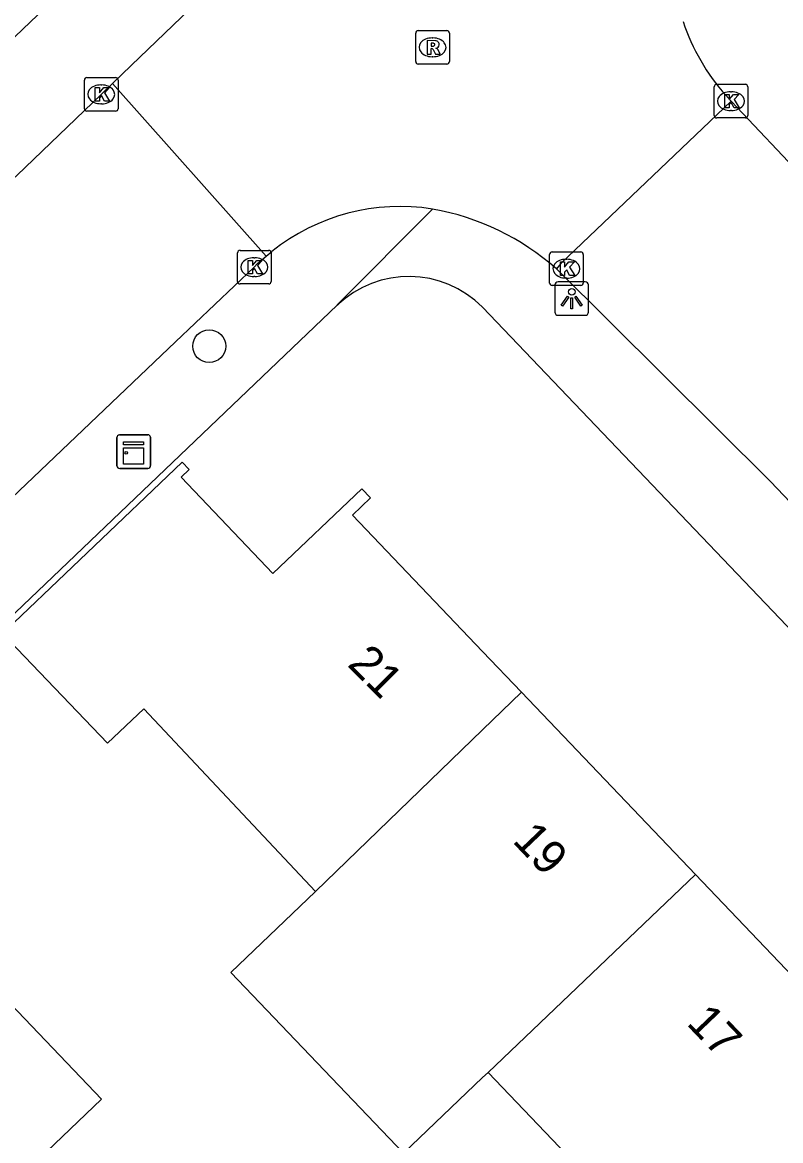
# Model space of a CAD drawing. Extents: x 159353 to 160616, y 385893 to 387321.
# Drawn here: x 159986.31 to 160008.86, y 386452.66 to 386485.93 of the extents above; entities that cross this region are included whole.
import ezdxf

# ---------------------------------------------------------------- set-up
doc = ezdxf.new("R2010")
doc.units = 0
for name, color, linetype in [('IMGEO_Boom', 7, 'Continuous'), ('IMGEO_Kast', 7, 'Continuous'), ('IMGEO_Kolk', 7, 'Continuous'), ('IMGEO_Lichtpunt', 7, 'Continuous'), ('IMGEO_Pand', 7, 'Continuous'), ('IMGEO_Pand_nummerreeks', 7, 'Continuous'), ('IMGEO_Rijbaan_lokaal_open', 7, 'Continuous'), ('IMGEO_Rioolput', 7, 'Continuous'), ('IMGEO_Voetpad_open', 7, 'Continuous')]:
    doc.layers.add(name, color=color, linetype=linetype)

msp = doc.modelspace()

# ---------------------------------------------------------------- linework, layer by layer
at = {"layer": 'IMGEO_Boom'}
msp.add_circle((159991.869, 386476.297), 0.489, dxfattribs=at)
at = {"layer": 'IMGEO_Kast'}
for p, q in [((159989.121, 386472.735), (159989.121, 386473.576)), ((159989.121, 386473.576), (159989.121, 386472.735)), ((159989.196, 386473.66), (159990.037, 386473.66)), ((159990.037, 386473.66), (159989.196, 386473.66)), ((159990.121, 386473.585), (159990.121, 386472.744)), ((159990.121, 386472.744), (159990.121, 386473.585)), ((159990.046, 386472.66), (159989.205, 386472.66)), ((159989.205, 386472.66), (159990.046, 386472.66))]:
    msp.add_line(p, q, dxfattribs=at)
for points in [[(159989.316, 386473.45), (159989.916, 386473.45), (159989.916, 386473.365), (159989.316, 386473.365), (159989.316, 386473.45)], [(159989.316, 386473.275), (159989.916, 386473.275), (159989.916, 386472.786), (159989.316, 386472.786), (159989.316, 386473.275)]]:
    msp.add_lwpolyline(points, dxfattribs=at)
msp.add_circle((159989.4, 386473.124), 0.0377, dxfattribs=at)
for centre, start, end in [((159989.199, 386473.582), 92.4484, 184.2845), ((159989.199, 386473.582), 92.4484, 184.2845), ((159990.043, 386473.582), 2.4484, 94.2845), ((159990.043, 386473.582), 2.4484, 94.2845), ((159989.199, 386472.738), 182.4484, 274.2845), ((159989.199, 386472.738), 182.4484, 274.2845), ((159990.043, 386472.738), 272.4484, 4.2845), ((159990.043, 386472.738), 272.4484, 4.2845)]:
    msp.add_arc(centre, 0.0779, start, end, dxfattribs=at)
at = {"layer": 'IMGEO_Kolk'}
for p, q in [((159988.156, 386483.363), (159988.156, 386484.215)), ((159988.231, 386484.289), (159989.083, 386484.289)), ((159989.157, 386484.215), (159989.157, 386483.363)), ((159988.644, 386484.069), (159988.669, 386484.069)), ((160006.887, 386483.161), (160006.887, 386484.013)), ((160006.962, 386484.087), (160007.814, 386484.087)), ((160007.375, 386483.867), (160007.4, 386483.867)), ((160007.888, 386484.013), (160007.888, 386483.161)), ((159988.667, 386483.509), (159988.642, 386483.509)), ((159989.083, 386483.289), (159988.231, 386483.289)), ((160007.398, 386483.307), (160007.373, 386483.307)), ((160007.814, 386483.087), (160006.962, 386483.087)), ((159992.784, 386479.148), (159993.636, 386479.148)), ((159992.709, 386478.222), (159992.709, 386479.074)), ((159993.197, 386478.928), (159993.222, 386478.928)), ((159993.71, 386479.074), (159993.71, 386478.222)), ((160001.993, 386478.176), (160001.993, 386479.028)), ((160002.068, 386479.102), (160002.92, 386479.102)), ((160002.481, 386478.882), (160002.506, 386478.882)), ((160002.994, 386479.028), (160002.994, 386478.176)), ((159993.636, 386478.148), (159992.784, 386478.148)), ((159993.22, 386478.368), (159993.195, 386478.368)), ((160002.504, 386478.322), (160002.479, 386478.322)), ((160002.92, 386478.102), (160002.068, 386478.102))]:
    msp.add_line(p, q, dxfattribs=at)
for points in [[(159988.156, 386483.363), (159988.156, 386484.215)], [(159988.231, 386484.289), (159989.083, 386484.289)], [(159989.157, 386484.215), (159989.157, 386483.363)], [(159988.477, 386483.989), (159988.6, 386483.989), (159988.6, 386483.838), (159988.73, 386483.989), (159988.894, 386483.989), (159988.748, 386483.838), (159988.901, 386483.589), (159988.749, 386483.589), (159988.664, 386483.753), (159988.6, 386483.686), (159988.6, 386483.589), (159988.477, 386483.589), (159988.477, 386483.989)], [(160006.887, 386483.161), (160006.887, 386484.013)], [(160006.962, 386484.087), (160007.814, 386484.087)], [(160007.888, 386484.013), (160007.888, 386483.161)], [(160007.208, 386483.787), (160007.331, 386483.787), (160007.331, 386483.636), (160007.461, 386483.787), (160007.625, 386483.787), (160007.479, 386483.636), (160007.632, 386483.387), (160007.48, 386483.387), (160007.395, 386483.551), (160007.331, 386483.484), (160007.331, 386483.387), (160007.208, 386483.387), (160007.208, 386483.787)], [(159989.083, 386483.289), (159988.231, 386483.289)], [(160007.814, 386483.087), (160006.962, 386483.087)], [(159992.784, 386479.148), (159993.636, 386479.148)], [(159992.709, 386478.222), (159992.709, 386479.074)], [(159993.03, 386478.848), (159993.153, 386478.848), (159993.153, 386478.697), (159993.283, 386478.848), (159993.447, 386478.848), (159993.301, 386478.697), (159993.454, 386478.448), (159993.302, 386478.448), (159993.217, 386478.612), (159993.153, 386478.545), (159993.153, 386478.448), (159993.03, 386478.448), (159993.03, 386478.848)], [(159993.71, 386479.074), (159993.71, 386478.222)], [(160001.993, 386478.176), (160001.993, 386479.028)], [(160002.068, 386479.102), (160002.92, 386479.102)], [(160002.994, 386479.028), (160002.994, 386478.176)], [(160002.314, 386478.802), (160002.437, 386478.802), (160002.437, 386478.651), (160002.567, 386478.802), (160002.731, 386478.802), (160002.585, 386478.651), (160002.738, 386478.402), (160002.586, 386478.402), (160002.501, 386478.566), (160002.437, 386478.499), (160002.437, 386478.402), (160002.314, 386478.402), (160002.314, 386478.802)], [(159993.636, 386478.148), (159992.784, 386478.148)], [(160002.92, 386478.102), (160002.068, 386478.102)]]:
    msp.add_lwpolyline(points, dxfattribs=at)
for centre, start, end in [((159988.233, 386484.213), 91.552, 178.448), ((159988.233, 386484.213), 91.552, 178.448), ((159989.081, 386484.213), 1.552, 88.448), ((159989.081, 386484.213), 1.552, 88.448), ((160006.964, 386484.011), 91.552, 178.448), ((160006.964, 386484.011), 91.552, 178.448), ((160007.812, 386484.011), 1.552, 88.448), ((160007.812, 386484.011), 1.552, 88.448), ((159988.233, 386483.365), 181.552, 268.448), ((159988.233, 386483.365), 181.552, 268.448), ((159989.081, 386483.365), 271.552, 358.448), ((159989.081, 386483.365), 271.552, 358.448), ((160006.964, 386483.163), 181.552, 268.448), ((160006.964, 386483.163), 181.552, 268.448), ((160007.812, 386483.163), 271.552, 358.448), ((160007.812, 386483.163), 271.552, 358.448), ((159992.786, 386479.072), 91.552, 178.448), ((159992.786, 386479.072), 91.552, 178.448), ((159993.634, 386479.072), 1.552, 88.448), ((159993.634, 386479.072), 1.552, 88.448), ((160002.07, 386479.026), 91.552, 178.448), ((160002.07, 386479.026), 91.552, 178.448), ((160002.918, 386479.026), 1.552, 88.448), ((160002.918, 386479.026), 1.552, 88.448), ((159992.786, 386478.224), 181.552, 268.448), ((159992.786, 386478.224), 181.552, 268.448), ((159993.634, 386478.224), 271.552, 358.448), ((159993.634, 386478.224), 271.552, 358.448), ((160002.07, 386478.178), 181.552, 268.448), ((160002.07, 386478.178), 181.552, 268.448), ((160002.918, 386478.178), 271.552, 358.448), ((160002.918, 386478.178), 271.552, 358.448)]:
    msp.add_arc(centre, 0.0765, start, end, dxfattribs=at)
for centre, major_axis, ratio, start_param, end_param in [((159988.643, 386483.789), (-0.387, 0.002), 0.722429, 4.712389, 7.853982), ((159988.668, 386483.789), (-0.39, 0.002), 0.717154, 1.570796, 4.712389), ((160007.374, 386483.587), (-0.387, 0.002), 0.722429, 4.712389, 7.853982), ((160007.399, 386483.587), (-0.39, 0.002), 0.717154, 1.570796, 4.712389), ((159993.196, 386478.648), (-0.387, 0.002), 0.722429, 4.712389, 7.853982), ((159993.221, 386478.648), (-0.39, 0.002), 0.717154, 1.570796, 4.712389), ((160002.48, 386478.602), (-0.387, 0.002), 0.722429, 4.712389, 7.853982), ((160002.505, 386478.602), (-0.39, 0.002), 0.717154, 1.570796, 4.712389)]:
    msp.add_ellipse(centre, major_axis=major_axis, ratio=ratio, start_param=start_param, end_param=end_param, dxfattribs=at)
at = {"layer": 'IMGEO_Lichtpunt'}
for p, q in [((160003.054, 386478.213), (160002.246, 386478.213)), ((160003.054, 386478.213), (160002.246, 386478.213)), ((160002.152, 386478.118), (160002.152, 386477.311)), ((160002.152, 386478.118), (160002.152, 386477.311)), ((160003.148, 386477.311), (160003.148, 386478.118)), ((160003.148, 386477.311), (160003.148, 386478.118)), ((160002.246, 386477.217), (160003.054, 386477.217)), ((160002.246, 386477.217), (160003.054, 386477.217))]:
    msp.add_line(p, q, dxfattribs=at)
for points in [[(160002.526, 386477.782), (160002.565, 386477.754), (160002.377, 386477.492), (160002.339, 386477.519), (160002.526, 386477.782)], [(160002.628, 386477.734), (160002.675, 386477.734), (160002.675, 386477.412), (160002.628, 386477.412), (160002.628, 386477.734)], [(160002.738, 386477.754), (160002.776, 386477.781), (160002.963, 386477.519), (160002.924, 386477.491), (160002.738, 386477.754)]]:
    msp.add_lwpolyline(points, dxfattribs=at)
msp.add_circle((160002.651, 386477.916), 0.0994, dxfattribs=at)
for centre, start, end in [((160002.246, 386478.118), 90, 180), ((160002.246, 386478.118), 90, 180), ((160003.054, 386478.118), 0, 90), ((160003.054, 386478.118), 0, 90), ((160002.246, 386477.311), 180, 270), ((160002.246, 386477.311), 180, 270), ((160003.054, 386477.311), 270, 0), ((160003.054, 386477.311), 270, 360)]:
    msp.add_arc(centre, 0.0946, start, end, dxfattribs=at)
at = {"layer": 'IMGEO_Pand'}
for points in [[(159995.032, 386460.069), (159989.925, 386465.51), (159988.846, 386464.481), (159985.932, 386467.534), (159985.613, 386467.23), (159985.405, 386467.447), (159991.062, 386472.845), (159991.269, 386472.627), (159991.03, 386472.399), (159993.763, 386469.533), (159996.403, 386472.052), (159996.66, 386471.783), (159996.126, 386471.273), (160000, 386467.212), (160001.152, 386466.004)], [(160001.152, 386466.004), (160000, 386464.887), (159995.032, 386460.069)], [(160001.152, 386466.004), (160006.33, 386460.577)], [(160000.162, 386454.692), (160006.33, 386460.577)], [(160006.33, 386460.577), (160011.508, 386455.149)], [(160000.162, 386454.692), (160000, 386454.537), (159997.644, 386452.29), (159992.514, 386457.667), (159995.032, 386460.069)], [(159980.895, 386456.885), (159983.455, 386459.336), (159988.663, 386453.897), (159986.103, 386451.446)], [(160004.961, 386448.904), (160004.871, 386448.998), (160005.25, 386449.36), (160000.162, 386454.692)]]:
    msp.add_lwpolyline(points, dxfattribs=at)
at = {"layer": 'IMGEO_Rijbaan_lokaal_open'}
for points in [[(159988.991, 386484.111), (159989.548, 386484.651), (159992.286, 386487.288), (160000, 386494.626), (160002.761, 386497.252)], [(159982.418, 386478.022), (159986.145, 386481.378), (159988.658, 386483.788), (159988.991, 386484.111)], [(159988.991, 386484.111), (159993.562, 386478.972)], [(160007.388, 386483.587), (160002.328, 386478.752), (160002.196, 386478.595)], [(160007.23, 386483.76), (160007.388, 386483.587)], [(160034.378, 386455.424), (160009.601, 386481.243), (160007.388, 386483.587)], [(159978.385, 386464.536), (159990.861, 386476.426), (159993.209, 386478.649), (159993.307, 386478.752), (159993.562, 386478.972)], [(159993.562, 386478.972), (159993.73, 386479.117)], [(160061.731, 386416.584), (160044.724, 386434.375), (160023.271, 386456.824), (160008.562, 386472.269), (160002.196, 386478.595)]]:
    msp.add_lwpolyline(points, dxfattribs=at)
for centre, radius, start, end in [((160011.931, 386487.938), 6.289, 198.4008, 221.6333), ((159997.556, 386474.302), 6.15, 81.045, 128.4716), ((159997.185, 386472.935), 7.559, 48.4788, 79.8817)]:
    msp.add_arc(centre, radius, start, end, dxfattribs=at)
at = {"layer": 'IMGEO_Rioolput'}
for p, q in [((159998.01, 386484.762), (159998.01, 386485.614)), ((159998.085, 386485.688), (159998.937, 386485.688)), ((159998.498, 386485.468), (159998.523, 386485.468)), ((159999.011, 386485.614), (159999.011, 386484.762)), ((159998.521, 386484.908), (159998.496, 386484.908)), ((159998.937, 386484.688), (159998.085, 386484.688))]:
    msp.add_line(p, q, dxfattribs=at)
for points in [[(159998.01, 386484.762), (159998.01, 386485.614)], [(159998.085, 386485.688), (159998.937, 386485.688)], [(159999.011, 386485.614), (159999.011, 386484.762)], [(159998.599, 386485.386), (159998.347, 386485.388), (159998.347, 386484.988)], [(159998.347, 386484.988), (159998.471, 386484.988), (159998.471, 386485.15), (159998.482, 386485.15)], [(159998.525, 386485.307), (159998.471, 386485.307), (159998.471, 386485.226)], [(159998.471, 386485.226), (159998.523, 386485.226)], [(159998.529, 386485.121), (159998.6, 386484.988), (159998.74, 386484.988), (159998.675, 386485.114)], [(159998.937, 386484.688), (159998.085, 386484.688)]]:
    msp.add_lwpolyline(points, dxfattribs=at)
for centre, radius, start, end in [((159998.087, 386485.612), 0.0765, 91.552, 178.448), ((159998.087, 386485.612), 0.0765, 91.552, 178.448), ((159998.935, 386485.612), 0.0765, 1.552, 88.448), ((159998.935, 386485.612), 0.0765, 1.552, 88.448), ((159998.481, 386485.097), 0.0533, 26.0293, 88.6989), ((159998.507, 386485.415), 0.19, 274.7715, 282.9687), ((159998.531, 386485.211), 0.0964, 77.0061, 93.1865), ((159998.545, 386485.268), 0.0378, 276.6634, 79.6772), ((159998.598, 386485.276), 0.109, 350.3612, 89.416), ((159998.596, 386485.276), 0.112, 277.5842, 350.9817), ((159998.58, 386485.061), 0.108, 29.5134, 73.7905), ((159998.087, 386484.764), 0.0765, 181.552, 268.448), ((159998.087, 386484.764), 0.0765, 181.552, 268.448), ((159998.935, 386484.764), 0.0765, 271.552, 358.448), ((159998.935, 386484.764), 0.0765, 271.552, 358.448)]:
    msp.add_arc(centre, radius, start, end, dxfattribs=at)
for centre, major_axis, ratio, start_param, end_param in [((159998.497, 386485.188), (-0.387, 0.002), 0.722429, 4.712389, 7.853982), ((159998.522, 386485.188), (-0.39, 0.002), 0.717154, 1.570796, 4.712389)]:
    msp.add_ellipse(centre, major_axis=major_axis, ratio=ratio, start_param=start_param, end_param=end_param, dxfattribs=at)
at = {"layer": 'IMGEO_Voetpad_open'}
for points in [[(159993.473, 386492.558), (159986.987, 386486.365), (159974.462, 386474.406)], [(159998.513, 386480.377), (159995.713, 386477.567), (159995.674, 386477.516)], [(159995.674, 386477.516), (159977.64, 386460.293)], [(160000, 386477.455), (160062.705, 386411.774)]]:
    msp.add_lwpolyline(points, dxfattribs=at)
msp.add_arc((159997.806, 386475.283), 3.087, 44.7109, 133.6734, dxfattribs=at)

# ---------------------------------------------------------------- texts
at = {"layer": 'IMGEO_Pand_nummerreeks'}
for s, rotation, p in [('21', 314.9342, (159995.951, 386466.805)), ('19', 313.6509, (160000.86, 386461.559)), ('17', 313.6509, (160006.038, 386456.131))]:
    msp.add_text(s, height=1, rotation=rotation, dxfattribs=at).set_placement(p)

doc.saveas('drawing.dxf')
